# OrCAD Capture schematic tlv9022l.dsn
size A
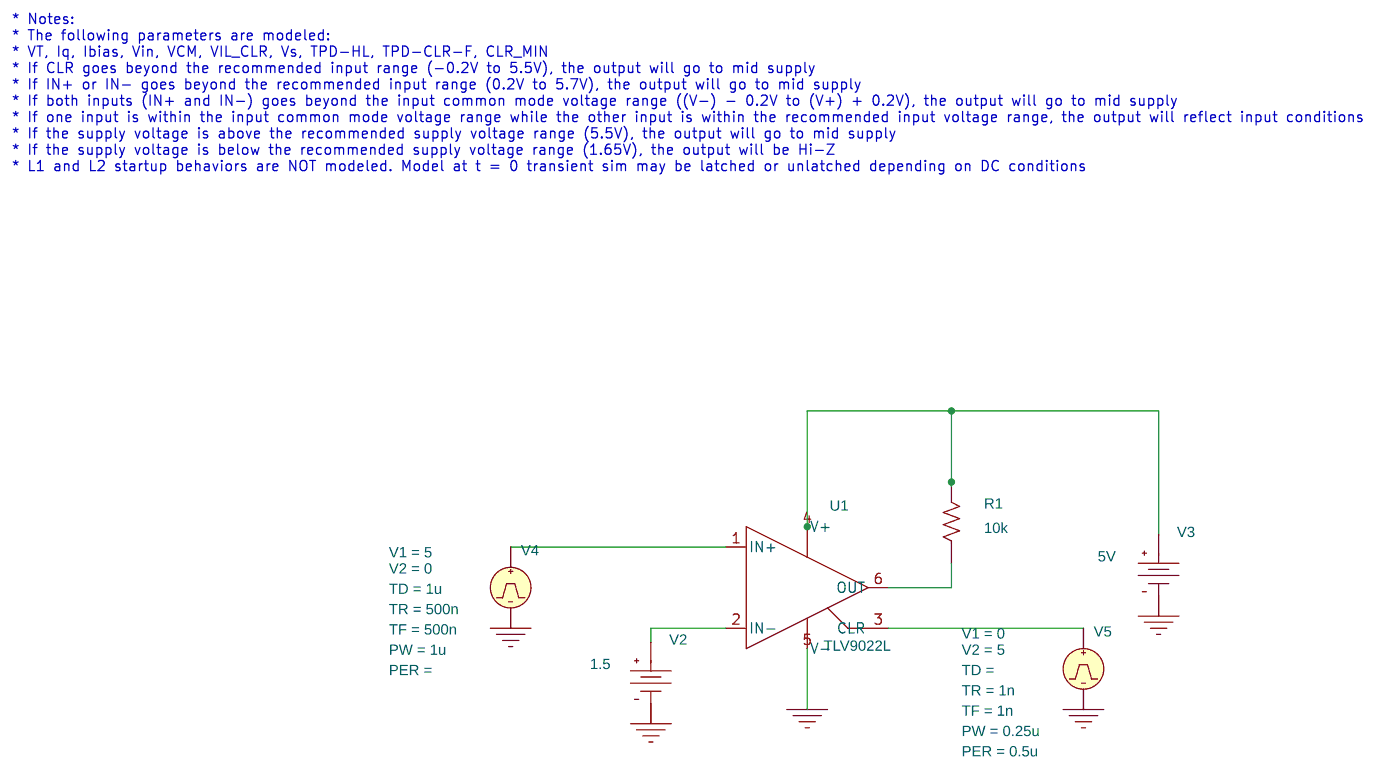
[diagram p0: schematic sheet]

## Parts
R1  10k  [AXRC05]
U1  TLV9022L
V2  VDC
V3  VDC
V4  VPULSE
V5  VPULSE

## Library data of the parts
R1 = R
U1 = TLV9022L
V2 = VDC: DC: 1.5
V3 = VDC: DC: 5V
V4 = VPULSE: PW: 1u; TD: 1u; TF: 500n; TR: 500n; V1: 5; V2: 0
V5 = VPULSE: PER: 0.5u; PW: 0.25u; TF: 1n; TR: 1n; V1: 0; V2: 5

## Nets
0: U1.5(V-) V2.1(-) V3.1(-) V4.2(-) V5.2(-)
N00178: U1.3(CLR) V5.1(+)
N00251: U1.2(IN-) V2.0(+)
N00316: R1.2 U1.4(V+) V3.0(+)
N00366: R1.1 U1.6(OUT)
N00516: U1.1(IN+) V4.1(+)

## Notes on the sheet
- * Notes:
  * The following parameters are modeled:
  * VT, Iq, Ibias, Vin, VCM, VIL_CLR, Vs, TPD-HL, TPD-CLR-F, CLR_MIN
  * If CLR goes beyond the recommended input range (-0.2V to 5.5V), the output will go to mid supply
  * If IN+ or IN- goes beyond the recommended input range (0.2V to 5.7V), the output will go to mid supply
  * If both inputs (IN+ and IN-) goes beyond the input common mode voltage range ((V-) - 0.2V to (V+) + 0.2V), the output will go to mid supply
  * If one input is within the input common mode voltage range while the other input is within the recommended input voltage range, the output will reflect input conditions
  * If the supply voltage is above the recommended supply voltage range (5.5V), the output will go to mid supply
  * If the supply voltage is below the recommended supply voltage range (1.65V), the output will be Hi-Z
  * L1 and L2 startup behaviors are NOT modeled. Model at t = 0 transient sim may be latched or unlatched depending on DC conditions
